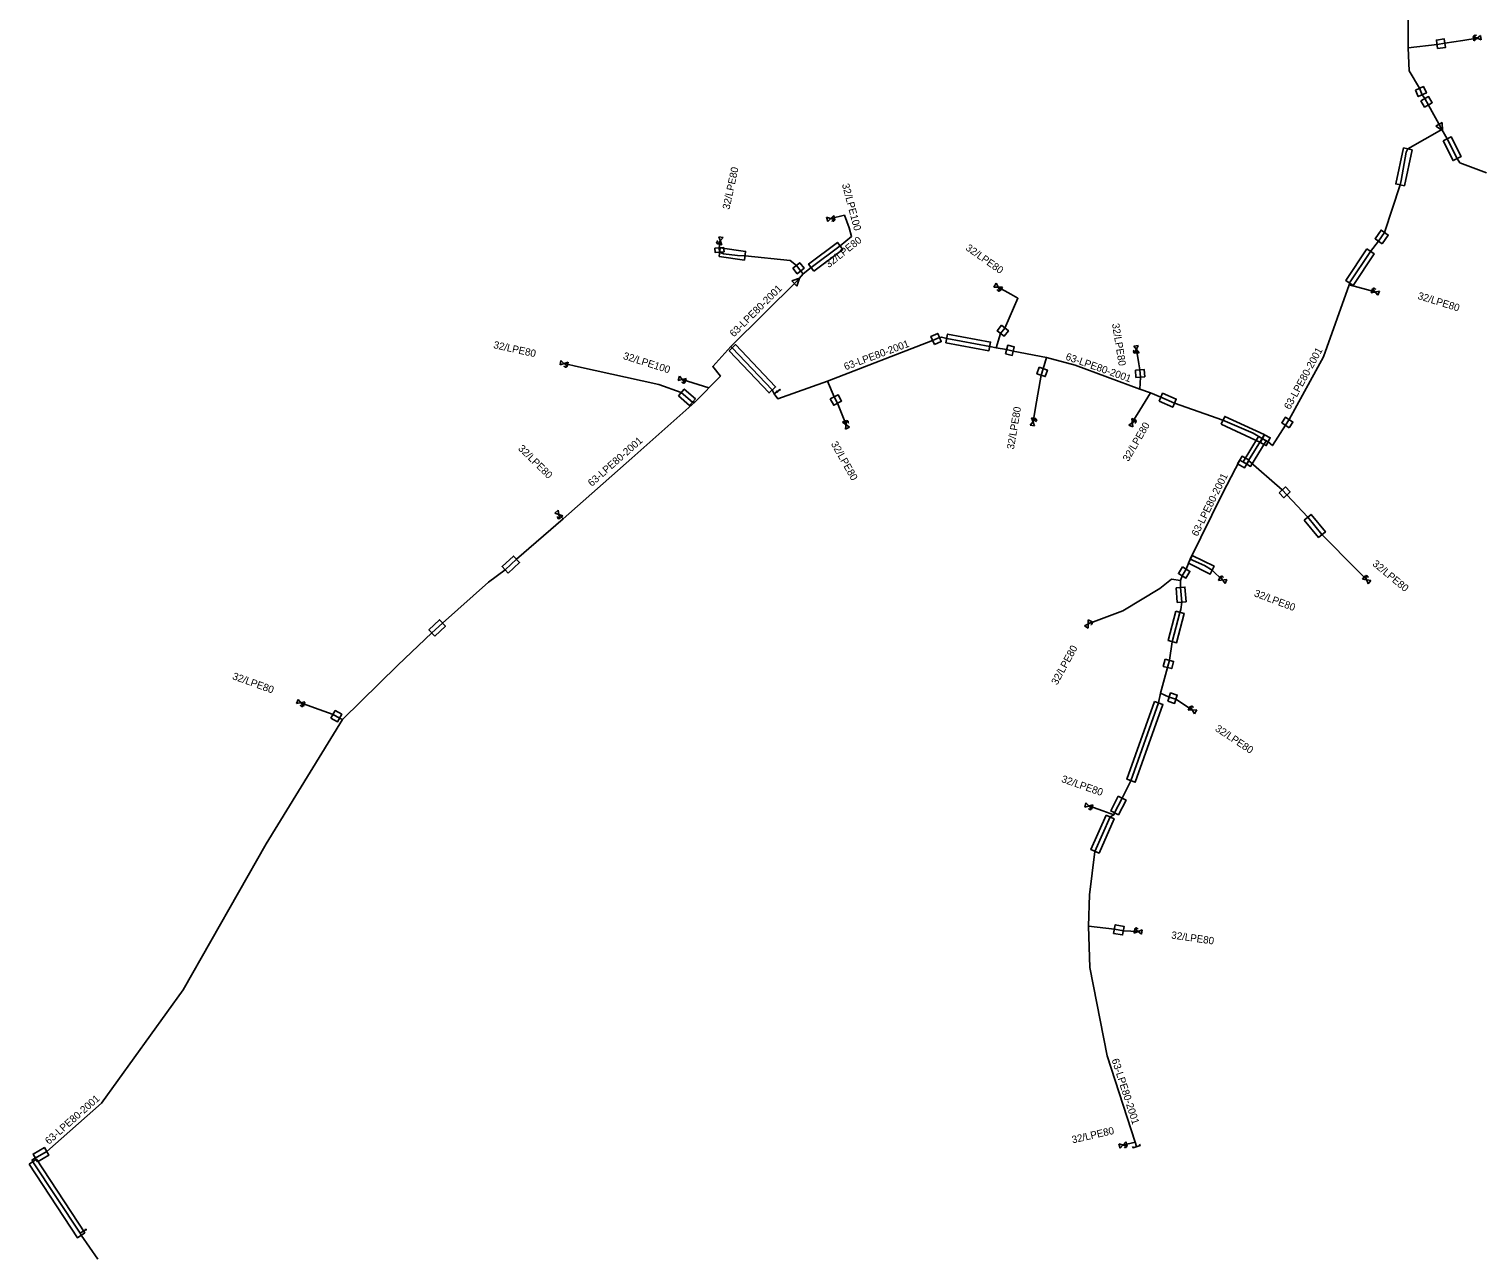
# Model space of a CAD drawing. Extents: x -787723 to -786204, y -1153846 to -1152384.
# Drawn here: x -786574.6 to -786376.3, y -1153635 to -1153467.7 of the extents above; entities that cross this region are included whole.
import ezdxf

# ---------------------------------------------------------------- set-up
doc = ezdxf.new("R2010")
doc.units = 0
for name, color, linetype in [('Vrstva 1', 7, 'Continuous'), ('Vrstva 21', 7, 'Continuous'), ('Vrstva 22', 7, 'Continuous'), ('Vrstva 26', 7, 'Continuous'), ('Vrstva 28', 7, 'Continuous'), ('Vrstva 29', 7, 'Continuous'), ('Vrstva 31', 7, 'Continuous'), ('Vrstva 32', 7, 'Continuous')]:
    doc.layers.add(name, color=color, linetype=linetype)

# ---------------------------------------------------------------- blocks, each defined once
blk = doc.blocks.new('DEC122')
at = {"layer": 'Vrstva 1'}
for p, q in [((-0.5, 0.5), (0.5, 0)), ((-0.5, -0.5), (-0.5, 0.5)), ((0.5, 0), (-0.5, -0.5))]:
    blk.add_line(p, q, dxfattribs=at)
blk = doc.blocks.new('DEC063-SN')
at = {"layer": 'Vrstva 1'}
for p, q in [((-0.5, -0.3), (0.5, 0.3)), ((0.5, -0.3), (-0.5, 0.3)), ((-0.5, 0.3), (-0.5, -0.3)), ((0.5, 0.3), (0.5, -0.3)), ((0.126, -0.318), (0.126, -0.458)), ((0.126, -0.384), (0.206, -0.384)), ((0.206, -0.458), (0.206, -0.318)), ((0.366, -0.458), (0.366, -0.318))]:
    blk.add_line(p, q, dxfattribs=at)
for points in [[(0.246, -0.318), (0.246, -0.418), (0.252, -0.438), (0.264, -0.451), (0.281, -0.458), (0.292, -0.458), (0.309, -0.451), (0.321, -0.438), (0.326, -0.418), (0.326, -0.318)], [(0.366, -0.318), (0.418, -0.318), (0.435, -0.325), (0.441, -0.331), (0.446, -0.344), (0.446, -0.364), (0.441, -0.378), (0.435, -0.384), (0.418, -0.391), (0.366, -0.391)]]:
    blk.add_lwpolyline(points, dxfattribs=at)
blk = doc.blocks.new('DEC130')
at = {"layer": 'Vrstva 1'}
blk.add_lwpolyline([(0.2, 0.5), (0, 0.5), (0, -0.5), (0.2, -0.5)], dxfattribs=at)
blk = doc.blocks.new('DEC127')
at = {"layer": 'Vrstva 1'}
for p, q in [((0, 0.56), (0, 0.99)), ((0, 0.42), (0, -0.01))]:
    blk.add_line(p, q, dxfattribs=at)
blk.add_lwpolyline([(-0.07, 0.82), (0, 0.99), (0.07, 0.82)], dxfattribs=at)
blk.add_circle((0, 0.49), 0.07, dxfattribs=at)

msp = doc.modelspace()

# ---------------------------------------------------------------- linework, layer by layer
at = {"layer": 'Vrstva 21'}
for points in [[(-786403.68, -1153426.09), (-786403.67, -1153426.59), (-786403.69, -1153429.66), (-786403.66, -1153430.4), (-786403.66, -1153431.35), (-786403.4, -1153433.13), (-786402.13, -1153440), (-786401.78, -1153441.05), (-786401.48, -1153442.23), (-786399.56, -1153445.43), (-786394.52, -1153452.17), (-786391.47, -1153455.66), (-786389.35, -1153457.6), (-786387.92, -1153458.78), (-786387.24, -1153460.52), (-786386.49, -1153465.07), (-786386.46, -1153466.99), (-786386.46, -1153470.29), (-786386.3, -1153473.43), (-786384.91, -1153475.81), (-786384.52, -1153476.69), (-786384.18, -1153477.22), (-786383.69, -1153478.09), (-786382, -1153481.15)], [(-786381.85, -1153481.41), (-786386.51, -1153484.08), (-786386.72, -1153484.54), (-786387.39, -1153488.4), (-786387.56, -1153488.99), (-786389.66, -1153495.5), (-786390.48, -1153496.68), (-786391.6, -1153498.06), (-786394.44, -1153502.37), (-786394.49, -1153502.64), (-786397.98, -1153512.45), (-786402.68, -1153521.02), (-786403.2, -1153521.79), (-786404.98, -1153524.56), (-786405.54, -1153524.03), (-786406.35, -1153523.61)], [(-786382, -1153481.15), (-786381.85, -1153481.41)], [(-786381.85, -1153481.41), (-786381.13, -1153482.7), (-786379.78, -1153485.4), (-786379.38, -1153485.98), (-786375.75, -1153487.36)], [(-786478.87, -1153511.03), (-786469.83, -1153502.08)], [(-786406.35, -1153523.61), (-786407.61, -1153522.88), (-786411.72, -1153521.11), (-786418.33, -1153518.77), (-786420.19, -1153517.97), (-786421.61, -1153517.37), (-786423.04, -1153516.88), (-786431.87, -1153513.6), (-786435.79, -1153512.53), (-786440.33, -1153511.67), (-786441.23, -1153511.45), (-786442.64, -1153511.2), (-786443.53, -1153511.03), (-786449.4, -1153509.93), (-786450.1, -1153509.75), (-786450.39, -1153509.81), (-786451.33, -1153510.22), (-786465.65, -1153515.77), (-786472.45, -1153518.17), (-786472.94, -1153517.5), (-786473.2, -1153516.96), (-786478.67, -1153511.2), (-786478.87, -1153511.03)], [(-786478.87, -1153511.03), (-786481.33, -1153513.77), (-786480.29, -1153515.07), (-786483.77, -1153518.64), (-786492.36, -1153526.29), (-786501.73, -1153534.54), (-786508.1, -1153540.08), (-786509.66, -1153541.52), (-786511.9, -1153543.21), (-786518.2, -1153548.77), (-786519.64, -1153550.13), (-786524.28, -1153554.5), (-786531.82, -1153561.95), (-786542.25, -1153578.91), (-786553.6, -1153598.82), (-786564.72, -1153614.27), (-786572.2, -1153620.86), (-786574.18, -1153622.01), (-786574.1, -1153622.28), (-786567.64, -1153632.02), (-786567.51, -1153632.31), (-786565.2, -1153635.57)], [(-786406.35, -1153523.61), (-786408.23, -1153526.61), (-786408.47, -1153527.09), (-786409.41, -1153526.53), (-786411.77, -1153531.09), (-786416.17, -1153540.08), (-786416.73, -1153541.41), (-786417.29, -1153542.33), (-786417.5, -1153542.99), (-786417.5, -1153543.91), (-786417.35, -1153545.92), (-786417.45, -1153546.92), (-786417.59, -1153547.32), (-786418.63, -1153551.32), (-786419.03, -1153553.86), (-786419.29, -1153554.84), (-786420.24, -1153558.33), (-786420.49, -1153559.67), (-786424.27, -1153570.29), (-786425.47, -1153572.66), (-786426.5, -1153574.67), (-786426.59, -1153574.93), (-786427.12, -1153575.23), (-786429.18, -1153579.93), (-786429.92, -1153585.85), (-786430.06, -1153590.13), (-786429.9, -1153595.78), (-786427.5, -1153607.85), (-786423.7, -1153619.62), (-786423.51, -1153620.22)]]:
    msp.add_lwpolyline(points, dxfattribs=at)
at = {"layer": 'Vrstva 29'}
for points in [[(-786382.43, -1153470.4), (-786382.59, -1153469.22), (-786381.53, -1153469.07), (-786381.37, -1153470.26)], [(-786385.46, -1153476.05), (-786384.36, -1153475.57), (-786383.97, -1153476.45), (-786385.07, -1153476.93)], [(-786384.7, -1153477.51), (-786383.66, -1153476.93), (-786383.17, -1153477.79), (-786384.21, -1153478.38)], [(-786381.67, -1153482.97), (-786380.59, -1153482.43), (-786379.24, -1153485.13), (-786380.32, -1153485.67)], [(-786387.1, -1153483.95), (-786385.92, -1153484.21), (-786386.97, -1153489.11), (-786388.15, -1153488.86)], [(-786389.99, -1153497.02), (-786390.97, -1153496.34), (-786390.15, -1153495.16), (-786389.17, -1153495.84)], [(-786481.04, -1153497.64), (-786479.84, -1153497.54), (-786479.79, -1153498.12), (-786480.99, -1153498.22)], [(-786480.47, -1153498.76), (-786480.31, -1153497.57), (-786476.84, -1153498.06), (-786477, -1153499.25)], [(-786467.54, -1153500.75), (-786468.26, -1153499.79), (-786464.32, -1153496.83), (-786463.6, -1153497.79)], [(-786392.1, -1153497.73), (-786391.1, -1153498.39), (-786393.94, -1153502.7), (-786394.94, -1153502.04)], [(-786470.39, -1153500.37), (-786469.45, -1153499.62), (-786468.86, -1153500.36), (-786469.8, -1153501.11)], [(-786441.93, -1153508.15), (-786440.99, -1153508.89), (-786441.58, -1153509.65), (-786442.52, -1153508.91)], [(-786451.09, -1153510.77), (-786451.57, -1153509.67), (-786450.63, -1153509.26), (-786450.15, -1153510.36)], [(-786449.51, -1153510.52), (-786449.29, -1153509.34), (-786443.42, -1153510.44), (-786443.64, -1153511.62)], [(-786479.1, -1153511.61), (-786478.23, -1153510.79), (-786472.76, -1153516.55), (-786473.64, -1153517.37)], [(-786441.37, -1153512.03), (-786441.09, -1153510.87), (-786440.19, -1153511.09), (-786440.47, -1153512.25)], [(-786436.81, -1153513.88), (-786435.67, -1153514.26), (-786435.96, -1153515.14), (-786437.1, -1153514.76)], [(-786423.66, -1153514.28), (-786422.46, -1153514.2), (-786422.39, -1153515.17), (-786423.59, -1153515.25)], [(-786486.02, -1153517.75), (-786485.22, -1153516.85), (-786483.69, -1153518.19), (-786484.48, -1153519.09)], [(-786465.29, -1153518.2), (-786464.23, -1153517.62), (-786463.76, -1153518.49), (-786464.82, -1153519.06)], [(-786420.43, -1153518.52), (-786419.95, -1153517.42), (-786418.09, -1153518.22), (-786418.57, -1153519.32)], [(-786411.97, -1153521.65), (-786411.47, -1153520.57), (-786406.1, -1153523.07), (-786406.6, -1153524.15)], [(-786402.7, -1153522.12), (-786403.7, -1153521.45), (-786403.18, -1153520.68), (-786402.18, -1153521.35)], [(-786406.86, -1153523.3), (-786405.84, -1153523.92), (-786407.96, -1153527.4), (-786408.98, -1153526.78)], [(-786406.63, -1153524.14), (-786406.07, -1153523.08), (-786405.26, -1153523.5), (-786405.82, -1153524.56)], [(-786409.72, -1153527.04), (-786409.1, -1153526.01), (-786408.16, -1153526.57), (-786408.78, -1153527.6)], [(-786404.06, -1153531.01), (-786403.18, -1153530.19), (-786402.55, -1153530.86), (-786403.43, -1153531.68)], [(-786400.62, -1153534.72), (-786399.7, -1153533.96), (-786397.75, -1153536.33), (-786398.67, -1153537.09)], [(-786509.25, -1153541.96), (-786510.07, -1153541.08), (-786508.51, -1153539.64), (-786507.69, -1153540.52)], [(-786416.44, -1153540.62), (-786415.9, -1153539.54), (-786412.92, -1153541.01), (-786413.46, -1153542.09)], [(-786417.24, -1153541.1), (-786416.22, -1153541.72), (-786416.78, -1153542.64), (-786417.8, -1153542.02)], [(-786418.1, -1153543.95), (-786416.9, -1153543.86), (-786416.75, -1153545.88), (-786417.95, -1153545.96)], [(-786418.17, -1153547.17), (-786417.01, -1153547.47), (-786418.05, -1153551.47), (-786419.21, -1153551.17)], [(-786519.23, -1153550.57), (-786520.05, -1153549.69), (-786518.61, -1153548.33), (-786517.79, -1153549.21)], [(-786419.61, -1153553.71), (-786418.45, -1153554.01), (-786418.71, -1153554.99), (-786419.87, -1153554.69)], [(-786421.06, -1153559.47), (-786419.92, -1153559.87), (-786423.7, -1153570.49), (-786424.83, -1153570.09)], [(-786419.23, -1153559.45), (-786418.87, -1153558.31), (-786417.95, -1153558.6), (-786418.31, -1153559.74)], [(-786533.43, -1153561.76), (-786532.83, -1153560.72), (-786531.94, -1153561.23), (-786532.54, -1153562.27)], [(-786426, -1153572.39), (-786424.94, -1153572.93), (-786425.97, -1153574.94), (-786427.03, -1153574.4)], [(-786427.67, -1153574.99), (-786426.57, -1153575.47), (-786428.63, -1153580.17), (-786429.73, -1153579.69)], [(-786426.64, -1153591.12), (-786426.42, -1153589.94), (-786425.2, -1153590.16), (-786425.42, -1153591.34)], [(-786573.45, -1153622.28), (-786574.05, -1153621.24), (-786572.5, -1153620.34), (-786571.9, -1153621.38)], [(-786574.6, -1153622.61), (-786573.6, -1153621.95), (-786567.01, -1153631.98), (-786568.01, -1153632.64)]]:
    msp.add_lwpolyline(points, close=True, dxfattribs=at)
at = {"layer": 'Vrstva 31'}
for points in [[(-786386.46, -1153470.29), (-786382.51, -1153469.81), (-786381.45, -1153469.67), (-786379.01, -1153469.28), (-786377.03, -1153468.97)], [(-786462.7, -1153494.87), (-786463.36, -1153493.13), (-786465.23, -1153493.56)], [(-786468.97, -1153501.12), (-786467.9, -1153500.27), (-786463.96, -1153497.31), (-786462.39, -1153496.04), (-786462.7, -1153494.87)], [(-786468.98, -1153501.13), (-786469.33, -1153500.74), (-786469.92, -1153500), (-786470.77, -1153499.29), (-786476.92, -1153498.66), (-786477.94, -1153498.62), (-786479.87, -1153498.4), (-786480.39, -1153498.17), (-786480.44, -1153497.59), (-786480.3, -1153496.61)], [(-786469.83, -1153502.08), (-786468.98, -1153501.13)], [(-786442.64, -1153511.2), (-786442.05, -1153509.28), (-786441.46, -1153508.52), (-786439.7, -1153504.46), (-786440.65, -1153503.91), (-786442.39, -1153502.93)], [(-786394.49, -1153502.64), (-786390.94, -1153503.6)], [(-786423.04, -1153516.88), (-786422.99, -1153515.21), (-786423.06, -1153514.24), (-786423.2, -1153513.41), (-786423.52, -1153511.44)], [(-786483.77, -1153518.64), (-786484.09, -1153518.64), (-786485.62, -1153517.3), (-786488.7, -1153516.24), (-786499.66, -1153513.8), (-786501.61, -1153513.37)], [(-786435.79, -1153512.53), (-786436.24, -1153514.07), (-786436.53, -1153514.95), (-786437.29, -1153519.35), (-786437.63, -1153521.32)], [(-786481.87, -1153516.69), (-786485.5, -1153515.53)], [(-786465.65, -1153515.77), (-786464.76, -1153517.91), (-786464.29, -1153518.78), (-786463.14, -1153521.72)], [(-786421.61, -1153517.37), (-786423.05, -1153519.71), (-786424.09, -1153521.42)], [(-786408.23, -1153526.61), (-786403.62, -1153530.6), (-786402.99, -1153531.27), (-786400.16, -1153534.34), (-786398.21, -1153536.71), (-786393.52, -1153541.45), (-786392.11, -1153542.87)], [(-786501.73, -1153534.54), (-786502.32, -1153533.96)], [(-786416.17, -1153540.08), (-786414.22, -1153540.92), (-786413.19, -1153541.55), (-786411.76, -1153542.91)], [(-786417.5, -1153542.99), (-786418.72, -1153542.79), (-786420.31, -1153544.05), (-786425.38, -1153547.13), (-786430.09, -1153548.9)], [(-786531.82, -1153561.95), (-786532.24, -1153561.75), (-786533.13, -1153561.24), (-786535.65, -1153560.33), (-786537.53, -1153559.65)], [(-786420.24, -1153558.33), (-786419.05, -1153558.88), (-786418.13, -1153559.17), (-786415.88, -1153560.66)], [(-786426.59, -1153574.93), (-786428.13, -1153574.39), (-786430.02, -1153573.73)], [(-786430.06, -1153590.13), (-786426.53, -1153590.53), (-786425.31, -1153590.75), (-786423.29, -1153590.86)], [(-786423.7, -1153619.62), (-786425.36, -1153620)]]:
    msp.add_lwpolyline(points, dxfattribs=at)

# ---------------------------------------------------------------- block references
at = {"layer": 'Vrstva 22', "rotation": 107.57125828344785}
msp.add_blockref('DEC130', (-786423.51, -1153620.22), dxfattribs=at)
at = {"layer": 'Vrstva 26'}
for p, rotation in [((-786382, -1153481.15), -61.06488610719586), ((-786469.83, -1153502.08), 44.713363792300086)]:
    msp.add_blockref('DEC122', p, dxfattribs=dict(at, rotation=rotation))
at = {"layer": 'Vrstva 28'}
for p, rotation in [((-786472.94, -1153517.5), -53.08058052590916), ((-786567.64, -1153632.02), -58.86808330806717)]:
    msp.add_blockref('DEC127', p, dxfattribs=dict(at, rotation=rotation))
at = {"layer": 'Vrstva 32'}
for p, rotation in [((-786377.03, -1153468.97), -173.13109451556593), ((-786465.23, -1153493.56), 13.348198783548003), ((-786480.3, -1153496.61), -100.38299720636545), ((-786442.39, -1153502.93), -31.677494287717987), ((-786390.94, -1153503.6), 160.52556396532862), ((-786423.52, -1153511.44), -83.91279165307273), ((-786501.61, -1153513.37), -12.435441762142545), ((-786485.5, -1153515.53), -17.61825840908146), ((-786463.14, -1153521.72), 113.47906110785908), ((-786437.63, -1153521.32), 80.20785278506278), ((-786424.09, -1153521.42), 66.61340279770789), ((-786502.32, -1153533.96), -48.48665548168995), ((-786411.76, -1153542.91), 155.3464582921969), ((-786392.11, -1153542.87), 139.9602333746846), ((-786430.09, -1153548.9), 59.17283055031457), ((-786537.53, -1153559.65), -19.885163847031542), ((-786415.88, -1153560.66), 151.1785139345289), ((-786430.02, -1153573.73), -15.037613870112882), ((-786423.29, -1153590.86), 172.6455889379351), ((-786425.36, -1153620), 16.51586668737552)]:
    msp.add_blockref('DEC063-SN', p, dxfattribs=dict(at, rotation=rotation))

# ---------------------------------------------------------------- texts
at = {"layer": 'Vrstva 21'}
for rotation, p in [(44.713, (-786478.44, -1153509.82)), (20.33, (-786463.21, -1153514.3)), (340.498, (-786433.27, -1153512.81)), (61.259, (-786402.59, -1153519.73)), (41.405, (-786497.83, -1153530.21)), (63.545, (-786415.19, -1153537.03)), (287.893, (-786426.92, -1153608.37)), (41.381, (-786571.9, -1153619.99))]:
    msp.add_text('63-LPE80-2001', height=1, rotation=rotation, dxfattribs=at).set_placement(p)
at = {"layer": 'Vrstva 31'}
for s, rotation, p in [('32/LPE80', 77.716, (-786479.05, -1153492.41)), ('32/LPE100', 284.931, (-786463.71, -1153488.93)), ('32/LPE80', 38.53, (-786465.5, -1153500.36)), ('32/LPE80', 324.802, (-786446.91, -1153497.8)), ('32/LPE80', 342.657, (-786385.22, -1153504.53)), ('32/LPE80', 279.226, (-786426.86, -1153507.95)), ('32/LPE80', 347.565, (-786511.31, -1153511.25)), ('32/LPE100', 342.382, (-786493.63, -1153512.72)), ('32/LPE80', 80.208, (-786440.25, -1153525.14)), ('32/LPE80', 59.846, (-786424.61, -1153526.82)), ('32/LPE80', 299.481, (-786465.24, -1153524.32)), ('32/LPE80', 315.49, (-786507.96, -1153525.05)), ('32/LPE80', 320.369, (-786391.42, -1153540.84)), ('32/LPE80', 339.326, (-786407.56, -1153545.09)), ('32/LPE80', 61.297, (-786434.34, -1153557.31)), ('32/LPE80', 340.115, (-786546.94, -1153556.41)), ('32/LPE80', 326.487, (-786412.88, -1153563.41)), ('32/LPE80', 340.75, (-786433.84, -1153570.45)), ('32/LPE80', 351.815, (-786418.82, -1153591.81)), ('32/LPE80', 12.894, (-786432.22, -1153619.78))]:
    msp.add_text(s, height=1, rotation=rotation, dxfattribs=at).set_placement(p)

doc.saveas('drawing.dxf')
